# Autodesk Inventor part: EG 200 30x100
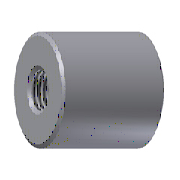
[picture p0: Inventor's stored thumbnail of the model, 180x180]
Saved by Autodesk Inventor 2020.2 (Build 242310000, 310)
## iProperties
Manager: www.cadconsulting.pl
Company: Fabian Stasiak CAD Consulting
Created: 2014-02
Part Number: EG 200 30x100
Material: DIN 1.7131
Description: Locating sleeves
Document SubType Name: Modeling
Designer: F.Stasiak
Standard Revision: 1
Manufacturer: DME
Language: pl-PL
Size Designation: 30x100
Categories: <MemberInstance><Categories><Category DisplayName="Forma wtryskowa" InternalName="349578f2-f4d4-4954-8c09-8e99297a61c0" Mnemonic="MOLD"><Category DisplayName="E
Mass: 1.68626 g
Surface Area: 16.3679 cm^2
Volume: 1.68626 cm^3
Density: 7.85 g/cm^3
Appearance: Stal
Catalog Web Link: www.expertbooks.pl
IsCustomPart: 0
Author: F.Stasiak
Subject: Zbiór ćwiczeń. Autodesk Inventor 2020. Kurs Professional
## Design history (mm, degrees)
sketch "Sketch1"
  geometry: L1 (0, -120)-(0, 20) reference; L2 (0, 0)-(15, 0); L3 (15, 0)-(15, -2.5); L4 (15, -2.5)-(14.99, -2.5); L5 (14.99, -2.5)-(14.99, -100); L6 (14.99, -100)-(12.5, -100); L7 (12.5, -100)-(12.5, -13); L8 (12.5, -13)-(6, -11); L9 (6, -11)-(0, -11); L10 (0, 0)-(0, -11); 1 further point
  constraints: 18 end point, 4 parallel, 3 perpendicular, 2 point on line, 1 coincident, 1 collinear
  dimensions: "d0" = 30 diameter of L3 L1 (= D); "d2" = 30 dimension on L5 L1 (= D_Guide); "d4" = 100 distance between parallel lines of L6 L2 (= L); "d5" = 25 diameter of L7 L1 (= d_); "d6" = 13 distance from line of L7.end L2 (= L1); "d7" = 2 distance from line of L7.end L9; "d8" = 12 diameter of L8.end L1 (= M); "d33" = 2.5 distance between parallel lines of L2 L4 (= L2)
revolve "Revolution1" sketch "Sketch1" stored, may be unused: angle "d9" = 90 deg
sketch "Sketch2"
  geometry: 1 further point
hole "Hole1" sketch "Sketch2" at (0, 0) diameter "d10" = 10.106; stored, may be unused: countersink angle "d14" = 90 deg, drill point angle "d16" = 0 deg; dims "d11" = 6, "d12" = 4, "d13" = 2, "d15" = 100 (= L)
chamfer "Chamfer1" distance "d17" = 0.5; stored, may be unused: second distance "d18" = 2, angle "d19" = 45 deg
fillet "Fillet1" dims "d30" = 0.5
body "Solid1"
other parameters: "D" = 30 [user parameter; used in 1 equation term], "L" = 100 [user parameter; used in 2 equation terms], "d_" = 25 [user parameter; used in 1 equation term], "M" = 12 [user parameter; used in 1 equation term], "L1" = 13 [user parameter; used in 1 equation term], "d22" = 0, "d31" = 0, "d32" = 0, "L2" = 2.5 [user parameter; used in 1 equation term]
